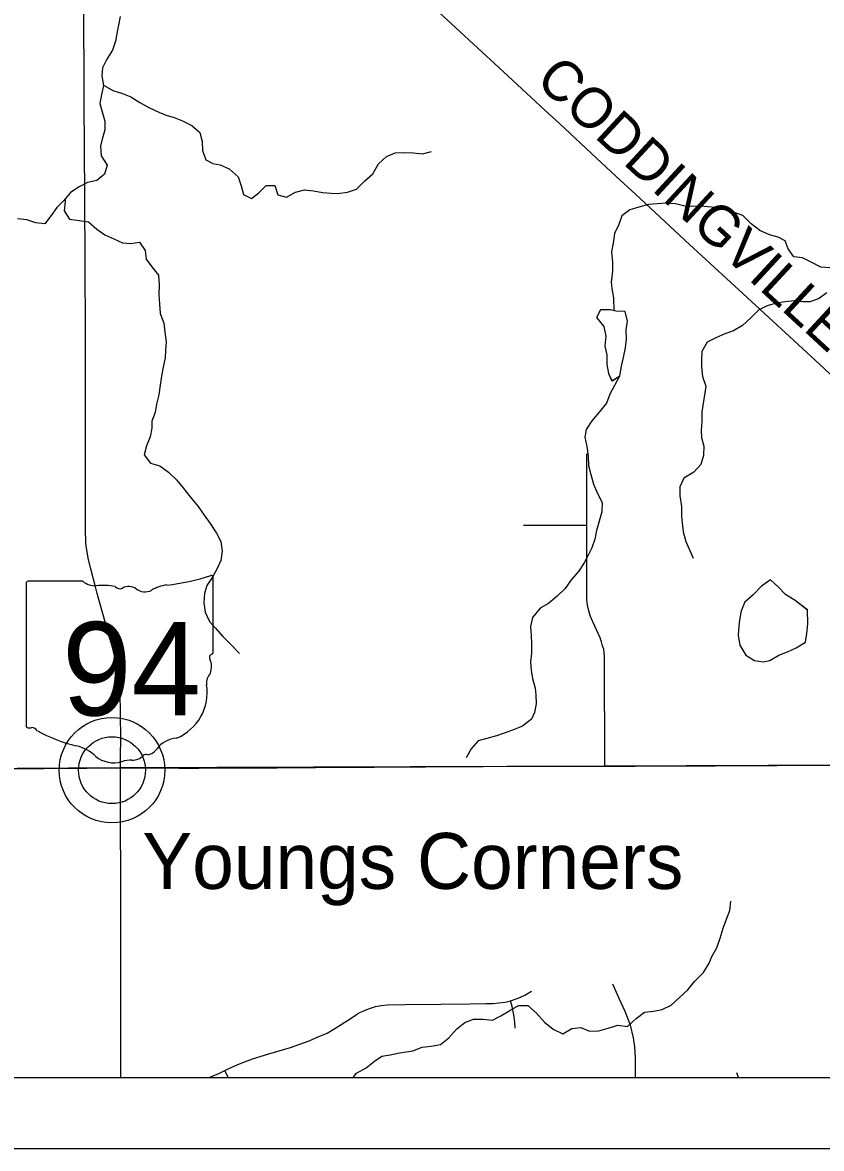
# Model space of a CAD drawing. Extents: x 0 to 34, y 0 to 22.
# Drawn here: x 5.327 to 6.454, y 14 to 15.589 of the extents above; entities that cross this region are included whole.
import ezdxf

# ---------------------------------------------------------------- set-up
doc = ezdxf.new("R2010")
doc.units = 0
for name, color, linetype in [('GM_X_Corporation', 7, 'Continuous'), ('GM_X_Minor_Lake', 7, 'Continuous'), ('GM_X_Minor_River', 7, 'Continuous'), ('GM_X_State_Location', 7, 'Continuous'), ('GM_X_State_Route', 7, 'Continuous'), ('GM_X_State_Shield', 7, 'Continuous'), ('GM_X_Township_Road', 7, 'Continuous'), ('GM_X_Township_Road_Text', 7, 'Continuous'), ('GM_X_Unincorporated', 7, 'Continuous'), ('GM_X_Unincorporated_Location', 7, 'Continuous'), ('GM_X_Unincorporated_Text', 7, 'Continuous'), ('SH_Data', 7, 'Continuous')]:
    doc.layers.add(name, color=color, linetype=linetype)

msp = doc.modelspace()

# ---------------------------------------------------------------- linework, layer by layer
at = {"layer": 'GM_X_Corporation'}
for points in [[(2.1, 20.9), (2.1, 14.1), (7.9734, 14.1), (7.9726, 14.5453), (7.9765, 15.2637), (7.9792, 15.5481), (7.979, 15.5988), (7.9808, 15.7192), (7.9807, 15.9078), (7.9821, 16.2487), (7.9825, 16.3395), (7.9818, 16.3982), (7.9825, 16.6077), (7.9838, 16.7968), (7.9877, 17.3871), (7.9891, 17.5498), (7.991, 17.7727), (7.9901, 18.1613)], [(7.9901, 18.1613), (7.991, 17.7727), (7.9891, 17.5498), (7.9877, 17.3871), (7.9838, 16.7968), (7.9825, 16.6077), (7.9818, 16.3982), (7.9825, 16.3395), (7.9821, 16.2487), (7.9807, 15.9078), (7.9808, 15.7192), (7.979, 15.5988), (7.9792, 15.5481), (7.9765, 15.2637), (7.9726, 14.5453), (7.0871, 14.5429), (7.0197, 14.5427), (6.4941, 14.5412), (6.1476, 14.5397), (5.4644, 14.5374), (4.5212, 14.531)]]:
    msp.add_lwpolyline(points, dxfattribs=at)
msp.add_lwpolyline([(2.8649, 14.1), (7.9734, 14.1), (7.9726, 14.5453), (7.0871, 14.5429), (7.0197, 14.5427), (6.4941, 14.5412), (6.1476, 14.5397), (5.4644, 14.5374), (4.5212, 14.531), (4.3772, 14.5296), (4.3422, 14.5307), (3.735, 14.5275), (3.3839, 14.5264), (3.3511, 14.525), (2.8655, 14.5214), (2.8638, 14.4461)], close=True, dxfattribs=at)
at = {"layer": 'GM_X_Minor_Lake'}
for points in [[(6.1642, 15.182), (6.1559, 15.1839), (6.1422, 15.1835), (6.1369, 15.1728), (6.1472, 15.1603), (6.1499, 15.1466), (6.1484, 15.1325), (6.1511, 15.1204), (6.1515, 15.1067), (6.1538, 15.0937), (6.1586, 15.0835)], [(6.164, 15.182), (6.1559, 15.1839), (6.1422, 15.1835), (6.1369, 15.1728), (6.1472, 15.1603), (6.1499, 15.1466), (6.1484, 15.1325), (6.1511, 15.1204), (6.1515, 15.1067), (6.1538, 15.0937), (6.1585, 15.0836)], [(6.1585, 15.0834), (6.1698, 15.0907), (6.172, 15.1044), (6.1747, 15.1166), (6.1777, 15.1299), (6.1792, 15.1428), (6.1788, 15.1554), (6.1803, 15.1679), (6.1772, 15.1812), (6.1639, 15.182)], [(6.1586, 15.0835), (6.1698, 15.0907), (6.172, 15.1044), (6.1747, 15.1166), (6.1777, 15.1299), (6.1792, 15.1428), (6.1788, 15.1554), (6.1803, 15.1679), (6.1772, 15.1812), (6.1642, 15.182)], [(6.4345, 14.7598), (6.4168, 14.7735), (6.4034, 14.7818), (6.3932, 14.7928), (6.3821, 14.8027), (6.3696, 14.7936), (6.3578, 14.7814), (6.346, 14.7711), (6.3407, 14.7589), (6.3384, 14.7456), (6.3369, 14.7319)], [(6.4346, 14.7596), (6.4168, 14.7735), (6.4034, 14.7818), (6.3932, 14.7928), (6.3821, 14.8027), (6.3696, 14.7936), (6.3578, 14.7814), (6.346, 14.7711), (6.3407, 14.7589), (6.3384, 14.7456), (6.3369, 14.7319)], [(6.3369, 14.7319), (6.3366, 14.7239), (6.3389, 14.7102), (6.3476, 14.6962), (6.3594, 14.689), (6.3716, 14.6867), (6.3811, 14.689), (6.3937, 14.6962), (6.4062, 14.7012), (6.4184, 14.7065), (6.4313, 14.7145), (6.4332, 14.7271), (6.4347, 14.7404), (6.4345, 14.7598)], [(6.3369, 14.7319), (6.3366, 14.7239), (6.3389, 14.7102), (6.3476, 14.6962), (6.3594, 14.689), (6.3716, 14.6867), (6.3811, 14.689), (6.3937, 14.6962), (6.4062, 14.7012), (6.4184, 14.7065), (6.4313, 14.7145), (6.4332, 14.7271), (6.4347, 14.7404), (6.4345, 14.7596)]]:
    msp.add_lwpolyline(points, dxfattribs=at)
at = {"layer": 'GM_X_Minor_River'}
for points in [[(5.4648, 15.5976), (5.4625, 15.5854), (5.4606, 15.5759), (5.4583, 15.5629), (5.4538, 15.55), (5.4462, 15.5374), (5.4397, 15.5253), (5.439, 15.5139), (5.4413, 15.5002), (5.4383, 15.4876), (5.436, 15.4751), (5.4395, 15.4633), (5.4433, 15.45), (5.4433, 15.4378), (5.4395, 15.4245), (5.4369, 15.4146), (5.438, 15.4013), (5.4464, 15.388), (5.4426, 15.3754), (5.432, 15.3663), (5.4187, 15.3636), (5.4069, 15.3571), (5.3947, 15.3491), (5.3856, 15.3381), (5.3753, 15.3282), (5.3674, 15.3168), (5.3586, 15.305), (5.3457, 15.3065), (5.3331, 15.3106), (5.3198, 15.3121)], [(5.4413, 15.5004), (5.4421, 15.5005), (5.4546, 15.4933), (5.468, 15.4892), (5.4801, 15.4842), (5.4927, 15.4763), (5.5053, 15.4694), (5.5194, 15.4626), (5.5296, 15.4584), (5.5411, 15.4554), (5.5529, 15.4505), (5.5658, 15.4437), (5.5772, 15.4338), (5.5803, 15.4212), (5.5811, 15.4087), (5.5857, 15.3954), (5.5956, 15.3901), (5.6058, 15.3882), (5.6188, 15.3829), (5.6314, 15.3715), (5.6356, 15.3586), (5.639, 15.3464), (5.65, 15.3407), (5.6603, 15.3487), (5.6709, 15.3594), (5.6831, 15.359), (5.6873, 15.3461), (5.6995, 15.3427), (5.712, 15.3499), (5.725, 15.3533), (5.7375, 15.3515), (5.7501, 15.3492), (5.7623, 15.3484), (5.7718, 15.3481), (5.7855, 15.3496), (5.798, 15.3542), (5.8098, 15.366), (5.8212, 15.3759), (5.8292, 15.3896), (5.8406, 15.4003), (5.8527, 15.4052), (5.8657, 15.406), (5.8782, 15.4053), (5.8912, 15.4037), (5.9041, 15.4072)], [(5.3874, 15.3402), (5.3871, 15.3366), (5.386, 15.3236), (5.3933, 15.3115), (5.407, 15.3096), (5.4203, 15.3081), (5.4317, 15.2975), (5.4431, 15.2895), (5.4557, 15.2838), (5.4679, 15.2781), (5.4797, 15.2774), (5.4922, 15.2793), (5.5002, 15.2675), (5.5014, 15.2553), (5.5094, 15.2443), (5.5189, 15.2325), (5.5197, 15.2188), (5.5194, 15.2055), (5.5205, 15.1922), (5.5213, 15.1785), (5.5266, 15.1648), (5.5278, 15.1523), (5.5297, 15.1386), (5.5286, 15.1261), (5.5282, 15.1162), (5.5256, 15.1029), (5.5233, 15.0903), (5.5211, 15.0774), (5.5196, 15.0637), (5.5162, 15.0507), (5.5143, 15.0389), (5.5097, 15.0264), (5.5094, 15.0169), (5.5071, 15.0043), (5.5022, 14.9918), (5.4988, 14.9792), (5.5075, 14.9674), (5.5208, 14.9637), (5.533, 14.9545), (5.5445, 14.9439), (5.5532, 14.9329), (5.5635, 14.92), (5.575, 14.9059), (5.5833, 14.8941), (5.5917, 14.882), (5.6009, 14.8687), (5.607, 14.8565), (5.6089, 14.8432), (5.607, 14.8299), (5.6017, 14.8185), (5.5953, 14.8063), (5.5873, 14.7945), (5.5839, 14.7831), (5.5828, 14.7702), (5.5847, 14.7568), (5.5908, 14.7439), (5.5992, 14.7344), (5.6095, 14.7226), (5.6209, 14.7113), (5.6331, 14.6987)], [(6.4659, 15.2428), (6.453, 15.244), (6.4397, 15.2508), (6.4275, 15.2572), (6.4153, 15.2584), (6.4073, 15.2698), (6.4027, 15.2812), (6.3932, 15.2861), (6.3806, 15.2895), (6.3673, 15.2956), (6.3551, 15.3051), (6.3429, 15.3168), (6.33, 15.3214), (6.3186, 15.3252), (6.3052, 15.3282), (6.2931, 15.3293), (6.2832, 15.3301), (6.2706, 15.3297), (6.2611, 15.33), (6.2482, 15.3331), (6.2352, 15.3342), (6.2223, 15.3334), (6.2101, 15.3323), (6.1964, 15.3288), (6.1839, 15.325), (6.1725, 15.3166), (6.1683, 15.3044), (6.1619, 15.2915), (6.16, 15.2778), (6.1577, 15.2656), (6.1593, 15.2508), (6.1593, 15.2379), (6.1574, 15.2234), (6.1585, 15.2139), (6.1605, 15.2006), (6.1614, 15.1826)], [(6.4614, 15.2078), (6.45, 15.1991), (6.4375, 15.1949), (6.428, 15.1949), (6.4158, 15.1964), (6.4028, 15.1952), (6.3903, 15.1933), (6.3774, 15.1895), (6.3652, 15.1834), (6.3546, 15.1723), (6.3428, 15.1617), (6.3299, 15.154), (6.3177, 15.1498), (6.3051, 15.1441), (6.293, 15.138), (6.2854, 15.1251), (6.2846, 15.1129), (6.2846, 15.1034), (6.2862, 15.0897), (6.2908, 15.076), (6.2893, 15.0665), (6.2855, 15.0399), (6.2851, 15.0266), (6.2844, 15.0133), (6.2848, 15.0034), (6.2879, 14.9912), (6.2875, 14.9783), (6.2841, 14.9654), (6.2742, 14.9547), (6.2601, 14.9459), (6.2541, 14.9341), (6.2545, 14.9212), (6.2568, 14.906), (6.2564, 14.8927), (6.2576, 14.8832), (6.2591, 14.8706), (6.2626, 14.8569), (6.2679, 14.8452), (6.2732, 14.833)], [(6.169, 15.0903), (6.1557, 15.0645), (6.1508, 15.0519), (6.1405, 15.0393), (6.1303, 15.0272), (6.1223, 15.0146), (6.1204, 15.0039), (6.1231, 14.991), (6.125, 14.9773), (6.1254, 14.964), (6.1289, 14.9511), (6.1327, 14.9378), (6.138, 14.9245), (6.1449, 14.9116), (6.1442, 14.8986), (6.1404, 14.8853), (6.1366, 14.8724), (6.1343, 14.8602), (6.1302, 14.848), (6.1256, 14.8385), (6.1195, 14.8267), (6.1112, 14.8145), (6.1009, 14.8024), (6.0926, 14.7902), (6.0812, 14.7795), (6.069, 14.7692), (6.0572, 14.7628), (6.0466, 14.7494), (6.0436, 14.7369), (6.0444, 14.7247), (6.0451, 14.7118), (6.0452, 14.6989), (6.0437, 14.6867), (6.0448, 14.6749), (6.0463, 14.6635), (6.0502, 14.6498), (6.0513, 14.6403), (6.0517, 14.6277), (6.0495, 14.6156), (6.0449, 14.6061), (6.0324, 14.5962), (6.0206, 14.5912), (6.0077, 14.5866), (5.9959, 14.5824), (5.9822, 14.5786), (5.97, 14.5752), (5.9597, 14.5641), (5.9529, 14.5512)], [(5.7936, 14.1), (5.7983, 14.1064), (5.812, 14.1137), (5.8234, 14.1232), (5.8341, 14.1304), (5.8458, 14.1323), (5.8588, 14.135), (5.8683, 14.1365), (5.8778, 14.1377), (5.8907, 14.143), (5.9037, 14.1446), (5.9166, 14.1469), (5.9284, 14.1564), (5.9394, 14.1686), (5.9508, 14.1777), (5.9633, 14.1827), (5.977, 14.1827), (5.99, 14.1812), (6.0018, 14.1873), (6.0143, 14.1949), (6.0269, 14.2018), (6.0398, 14.2018), (6.052, 14.1908), (6.0634, 14.1782), (6.0756, 14.1684), (6.0893, 14.1619), (6.1019, 14.1692), (6.1148, 14.1707), (6.127, 14.1654), (6.1399, 14.1662), (6.1532, 14.17), (6.1669, 14.1742), (6.1806, 14.1723), (6.1928, 14.1833), (6.2042, 14.1925), (6.2171, 14.1936), (6.2293, 14.1963), (6.2422, 14.2024), (6.254, 14.2131), (6.2654, 14.2241), (6.2749, 14.2359), (6.2878, 14.2485), (6.2958, 14.2614), (6.2992, 14.2709), (6.3064, 14.2831), (6.3113, 14.2968), (6.3155, 14.3109), (6.32, 14.3238), (6.3246, 14.336), (6.3261, 14.3493)]]:
    msp.add_lwpolyline(points, dxfattribs=at)
at = {"layer": 'GM_X_State_Route'}
msp.add_line((5.4659, 14.1), (5.4656, 14.342), dxfattribs=at)
for points in [[(5.4653, 14.5373), (5.4655, 14.5536), (5.4659, 14.5787), (5.4655, 14.6133), (5.4649, 14.6435), (5.464, 14.6567), (5.4636, 14.6622), (5.4627, 14.6686), (5.4608, 14.6781), (5.4589, 14.687), (5.4544, 14.7057), (5.4504, 14.72), (5.4461, 14.7348), (5.4389, 14.7596), (5.4324, 14.7834), (5.4299, 14.7926), (5.4238, 14.8162), (5.4228, 14.8196), (5.4197, 14.8332), (5.4186, 14.8392), (5.4177, 14.8444), (5.4173, 14.8479), (5.4166, 14.8545), (5.4163, 14.8608), (5.4161, 14.8678), (5.4159, 14.8926), (5.4157, 15.1232), (5.4154, 15.278), (5.4151, 15.313), (5.4149, 15.3628), (5.4147, 15.3913), (5.4146, 15.4096), (5.4142, 15.4787), (5.4139, 15.5354), (5.4137, 15.569), (5.4134, 15.6126)], [(5.2966, 14.5358), (5.4176, 14.5369), (5.4653, 14.5373), (5.5015, 14.5374), (5.5478, 14.5369), (5.5757, 14.537), (5.6034, 14.5371), (5.6312, 14.5372), (5.6591, 14.5374), (5.6862, 14.5375), (5.7139, 14.5376), (5.7402, 14.5378), (5.7679, 14.538), (5.7957, 14.5382), (5.8232, 14.5384), (5.8516, 14.5386), (5.8956, 14.5389), (5.939, 14.5392), (5.9767, 14.5393), (6.036, 14.5395), (6.0646, 14.5395), (6.0942, 14.5396), (6.1485, 14.5397), (6.1914, 14.5398), (6.2244, 14.5399), (6.2414, 14.54), (6.2727, 14.5401), (6.304, 14.5402), (6.3352, 14.5404), (6.3775, 14.5405), (6.3911, 14.5406), (6.4204, 14.5408), (6.4465, 14.5409), (6.4708, 14.541)], [(5.4656, 14.342), (5.4656, 14.357), (5.4653, 14.4856), (5.4653, 14.5373)]]:
    msp.add_lwpolyline(points, dxfattribs=at)
at = {"layer": 'GM_X_State_Shield'}
for p, q in [((5.3323, 14.7972), (5.3323, 14.597)), ((5.4121, 14.8006), (5.3349, 14.8006)), ((5.596, 14.7009), (5.596, 14.8056)), ((5.596, 14.7009), (5.596, 14.7009))]:
    msp.add_line(p, q, dxfattribs=at)
for centre, radius, start, end in [((5.3353, 14.7976), 0.00305, 98.1301, 188.1301), ((5.4305, 14.8238), 0.0296, 231.6195, 271.1119), ((5.5021, 15.0734), 0.2796, 275.8445, 288.9065), ((5.5931, 14.806), 0.00294, 351.8621, 97.738), ((5.4403, 14.6883), 0.1064, 80.4867, 94.9883), ((5.4645, 14.7986), 0.00855, 219.7921, 297.1024), ((5.477, 14.7755), 0.0178, 54.4667, 119.1411), ((5.5, 14.8072), 0.0214, 233.8562, 294.8282), ((5.5377, 14.7395), 0.0563, 97.3462, 120.7689), ((5.5929, 14.7005), 0.00314, 289.6038, 7.7341), ((5.5953, 14.6932), 0.00454, 107.944, 210.337), ((5.5664, 14.68), 0.0273, 340.033, 23.6496), ((5.6065, 14.6571), 0.0198, 136.8065, 186.9296), ((5.5177, 14.6438), 0.0699, 292.3089, 8.9858), ((5.3354, 14.5966), 0.00308, 171.9584, 258.3066), ((5.3358, 14.6171), 0.0235, 267.339, 280.6039), ((5.3406, 14.5855), 0.00848, 29.7484, 93.2717), ((5.4477, 14.7653), 0.2019, 240.4129, 257.1985), ((5.5472, 14.5409), 0.0383, 94.4031, 142.5768), ((5.3875, 14.5071), 0.0632, 47.1842, 75.836), ((5.4987, 14.5776), 0.0226, 282.8732, 323.2771), ((5.4558, 14.5845), 0.0401, 230.7004, 286.2918), ((5.479, 14.5153), 0.0329, 85.6951, 111.2099), ((5.4819, 14.5695), 0.0214, 268.777, 315.5493), ((5.5013, 14.5501), 0.00601, 65.7517, 132.6484)]:
    msp.add_arc(centre, radius, start, end, dxfattribs=at)
at = {"layer": 'GM_X_Township_Road'}
for p, q in [((6.0337, 14.8796), (6.1229, 14.88)), ((5.6173, 14.1), (5.6123, 14.11)), ((6.3368, 14.1), (6.3345, 14.107))]:
    msp.add_line(p, q, dxfattribs=at)
for points in [[(6.4815, 15.0788), (6.4512, 15.1068), (6.3374, 15.212), (6.2679, 15.2761), (6.1915, 15.347), (6.165, 15.3716), (6.1642, 15.3724), (6.1365, 15.398), (6.0843, 15.4465), (6.0641, 15.4653), (6.0441, 15.4838), (5.9928, 15.5314), (5.9753, 15.5476), (5.9317, 15.588), (5.8929, 15.624)], [(6.1485, 14.5397), (6.1482, 14.6944), (6.1475, 14.6996), (6.1469, 14.7047), (6.1454, 14.7096), (6.1439, 14.715), (6.1417, 14.7206), (6.1397, 14.7261), (6.1315, 14.7434), (6.1284, 14.7509), (6.1259, 14.7589), (6.1241, 14.7668), (6.1234, 14.7708), (6.1231, 14.775), (6.1229, 14.7809), (6.1229, 14.88), (6.1233, 14.9804)], [(6.1919, 14.1), (6.1918, 14.1281), (6.1906, 14.1436), (6.189, 14.1561), (6.1847, 14.1742), (6.1772, 14.1935), (6.1689, 14.2119), (6.1599, 14.2317)], [(5.5898, 14.1), (5.5911, 14.1005), (5.6042, 14.106), (5.6123, 14.11), (5.6234, 14.1151), (5.633, 14.1195), (5.6513, 14.1264), (5.6747, 14.1334), (5.7049, 14.1426), (5.7315, 14.1519), (5.742, 14.1565), (5.7566, 14.1628), (5.7678, 14.1694), (5.7906, 14.1841), (5.7998, 14.1901), (5.8037, 14.1923), (5.8083, 14.1945), (5.8163, 14.1977), (5.8251, 14.2004), (5.8328, 14.2017), (5.842, 14.2027), (5.8663, 14.2032), (5.917, 14.2036), (5.958, 14.2041), (5.9806, 14.2044), (5.9908, 14.2048), (5.999, 14.2055), (6.0081, 14.2066), (6.0155, 14.2084), (6.026, 14.2122), (6.0354, 14.2165), (6.0452, 14.222)], [(6.0218, 14.1696), (6.0213, 14.1785), (6.02, 14.1886), (6.0176, 14.2004), (6.0155, 14.2084)]]:
    msp.add_lwpolyline(points, dxfattribs=at)
at = {"layer": 'GM_X_Unincorporated'}
for radius in [0.0744, 0.0472]:
    msp.add_circle((5.4533, 14.5339), radius, dxfattribs=at)
at = {"layer": 'GM_X_Unincorporated_Location'}
msp.add_line((5.4533, 14.5339), (5.4533, 14.5339), dxfattribs=at)
at = {"layer": 'SH_Data'}
for p, q in [((2.1, 14.1), (8.9, 14.1)), ((2, 14), (9, 14))]:
    msp.add_line(p, q, dxfattribs=at)

# ---------------------------------------------------------------- texts
at = {"layer": 'GM_X_State_Location'}
msp.add_text('94', height=0.000189, rotation=0, dxfattribs=at).set_placement((5.4135, 14.67))
for s in ['s', 'r']:
    msp.add_text(s, height=0.000189, dxfattribs=at).set_placement((5.4612, 14.6838))
at = {"layer": 'GM_X_State_Shield'}
msp.add_text('94', height=0.13184, dxfattribs=at).set_placement((5.3829, 14.6112))
at = {"layer": 'GM_X_Township_Road_Text'}
msp.add_text('CODDINGVILLE', height=0.056818, rotation=317.2645, dxfattribs=at).set_placement((6.0487, 15.5053))
at = {"layer": 'GM_X_Unincorporated_Text'}
msp.add_text('Youngs Corners', height=0.078977, rotation=0, dxfattribs=at).set_placement((5.496, 14.3664))

doc.saveas('drawing.dxf')
